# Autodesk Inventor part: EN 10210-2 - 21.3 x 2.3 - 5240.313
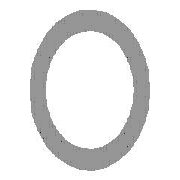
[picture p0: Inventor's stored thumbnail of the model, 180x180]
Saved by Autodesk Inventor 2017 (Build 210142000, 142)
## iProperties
Created: 2016-02
Part Number: EN 10210-2 - 21.3 x 2.3 - 5240.313
Material: Steel, Mild
Description: Pipe
Document SubType Name: Modeling
Standard: DIN
Designer: iusti
Standard Revision: 2006-07
Standards Organization: DIN
Language: en-US
Size Designation: 21.3 x 2.3
Categories: <MemberInstance><Categories><Category DisplayName="Structural Shapes" InternalName="089c4875-fa83-4c05-b084-43b9cc11f5ed" Mnemonic="GRDR"><CategoryParameter Dis
Stock Number: 21.3 x 2.3
Density: 7.85 g/cm^3
Appearance: Semi-Polished
IsCustomPart: 1
G_L: 5240.313 mm
G_W: 21.300 mm
G_H: 21.300 mm
_CCFamilyMember: 1
_CCFamilyDisplayName: DIN EN 10210-2 - Pipe
_FrameMemberDoc: Frame Member File
_Version: 15.0.0
_GetPNFromCC: 1
Author: iusti
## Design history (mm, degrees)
node "Start plane"
node "End plane"
sketch "Sketch"
  geometry: C1 r 8.35 at (0, 0); C2 r 10.65 at (0, 0); 2 further points
  constraints: 3 coincident, 2 centre point
  dimensions: "d0" = 21.3 diameter of C2 (= G_H); "d1" = 2.3 radial gap between concentric circles of C2 C1 (= G_T)
extrude "Body" new body sketch "Sketch" stored distance "d2" = 5240.31264 (= G_L); taper "d3" = 0 deg
node "Driven Length"
  sketch "Sketch3"
    geometry: L1 (0, 0)-(10, 0) reference
    constraints: 2 end point, 1 horizontal
  workplane "Work Plane3"
  sketch "Sketch4"
    geometry: L1 (-2, 0)-(12, 0) reference; L2 (-2, 5240.313)-(12, 5240.313) reference
    dimensions: "d7" = 5240.31264 distance between parallel lines of L1 L2 (derived)
body "Solid1"
other parameters: "G_H" = 21.3 [user parameter; used in 1 equation term], "G_T" = 2.3 [user parameter; used in 1 equation term], "G_L" = 5240.31264 (= d7) [user parameter; used in 1 equation term], "G_OFFSET_START" = 0 [user parameter; used in 1 equation term], "G_OFFSET_END" = 0 [user parameter; used in 1 equation term], "d4" = 0 (computed from G_OFFSET_START), "d5" = 5240.31264 (= G_OFFSET_END + B_L), "B_L" = 5240.31264 [user parameter; used in 1 equation term], "d6" = 90 deg
